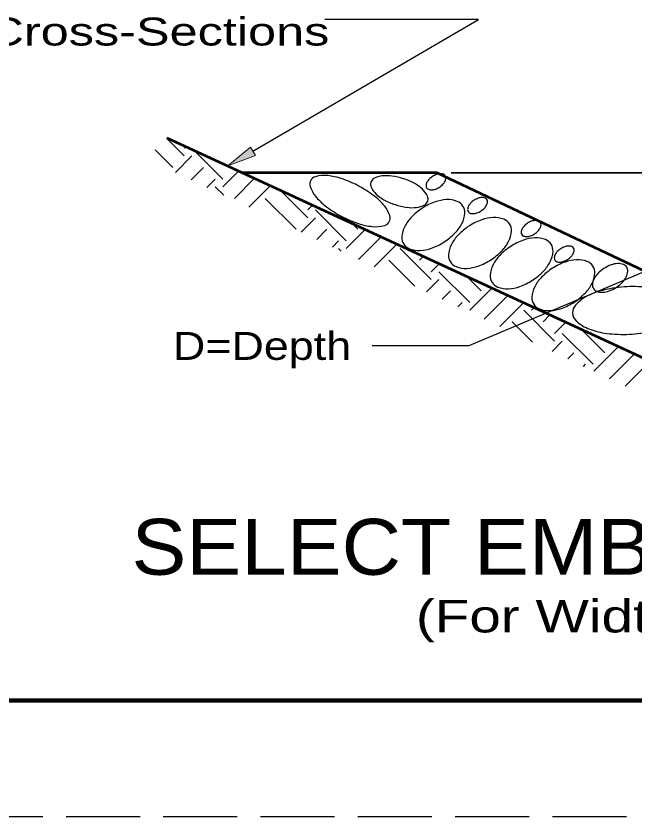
# Model space of a CAD drawing. Extents: x 72.6 to 107.3, y 36.1 to 58.1.
# Drawn here: x 93.671 to 96.33, y 36.08 to 39.52 of the extents above; entities that cross this region are included whole.
import ezdxf

# ---------------------------------------------------------------- set-up
doc = ezdxf.new("R2010")
doc.units = 0
doc.header["$LTSCALE"] = 0.053
doc.linetypes.add('LONG_DASHED', pattern=[7.5, 6, -1.5])
for name, color, linetype, lineweight in [('1', 7, 'Continuous', 35), ('3', 7, 'Continuous', 13), ('4', 7, 'Continuous', 25), ('6', 7, 'Continuous', 13)]:
    doc.layers.add(name, color=color, linetype=linetype, lineweight=lineweight)

msp = doc.modelspace()

# ---------------------------------------------------------------- hatches: boundary and pattern name
at = {"layer": '3'}
msp.add_hatch(color=256, dxfattribs=at).paths.add_polyline_path([(94.69917, 38.92083), (94.67825, 38.95683), (94.58075, 38.87583), (94.58075, 38.87583)])

# ---------------------------------------------------------------- linework, layer by layer
at = {"layer": '1', "lineweight": 25}
for p, q in [((94.39383, 38.91867), (94.31708, 38.9955)), ((94.39383, 38.91867), (94.31708, 38.9955)), ((94.34408, 38.869), (94.2685, 38.94458)), ((94.34408, 38.869), (94.2685, 38.94458)), ((94.39383, 38.95183), (94.40092, 38.95892)), ((94.39383, 38.95183), (94.40092, 38.95892)), ((94.55958, 38.81925), (94.43625, 38.94258)), ((94.55958, 38.81925), (94.43625, 38.94258)), ((94.35608, 38.84783), (94.427, 38.91867)), ((94.35608, 38.84783), (94.427, 38.91867)), ((94.4235, 38.81575), (94.47667, 38.869)), ((94.4235, 38.81575), (94.47667, 38.869)), ((94.55958, 38.78608), (94.62758, 38.85417)), ((94.55958, 38.78608), (94.62758, 38.85417)), ((94.49092, 38.78375), (94.52642, 38.81925)), ((94.49092, 38.78375), (94.52642, 38.81925)), ((94.60925, 38.73642), (94.69558, 38.82275)), ((94.60925, 38.73642), (94.69558, 38.82275)), ((94.56308, 38.7495), (94.52642, 38.78608)), ((94.56308, 38.7495), (94.52642, 38.78608)), ((94.67067, 38.69833), (94.76358, 38.79133)), ((94.67067, 38.69833), (94.76358, 38.79133)), ((94.92417, 38.6535), (94.806, 38.77175)), ((94.92417, 38.6535), (94.806, 38.77175)), ((94.87442, 38.60383), (94.74183, 38.73642)), ((94.87442, 38.60383), (94.74183, 38.73642)), ((94.87442, 38.73642), (94.877, 38.73892)), ((94.87442, 38.73642), (94.877, 38.73892)), ((94.92417, 38.68667), (94.945, 38.7075)), ((94.92417, 38.68667), (94.945, 38.7075)), ((95.08992, 38.55408), (94.95733, 38.68667)), ((95.08992, 38.55408), (94.95733, 38.68667)), ((94.89533, 38.59158), (94.95733, 38.6535)), ((94.89533, 38.59158), (94.95733, 38.6535)), ((95.13958, 38.60383), (95.11408, 38.62933)), ((95.13958, 38.60383), (95.11408, 38.62933)), ((94.96275, 38.55958), (95.007, 38.60383)), ((94.96275, 38.55958), (95.007, 38.60383)), ((95.08992, 38.52092), (95.17167, 38.60275)), ((95.08992, 38.52092), (95.17167, 38.60275)), ((95.1425, 38.47417), (95.23967, 38.57125)), ((95.1425, 38.47417), (95.23967, 38.57125)), ((95.03017, 38.5275), (95.05675, 38.55408)), ((95.03017, 38.5275), (95.05675, 38.55408)), ((95.20992, 38.44208), (95.30767, 38.53983)), ((95.20992, 38.44208), (95.30767, 38.53983)), ((95.06825, 38.50942), (95.05675, 38.52092)), ((95.06825, 38.50942), (95.05675, 38.52092)), ((95.4545, 38.38833), (95.32192, 38.52092)), ((95.4545, 38.38833), (95.32192, 38.52092)), ((95.38408, 38.35942), (95.27217, 38.47125)), ((95.38408, 38.35942), (95.27217, 38.47125)), ((95.40475, 38.47125), (95.421, 38.4875)), ((95.40475, 38.47125), (95.421, 38.4875)), ((95.4545, 38.4215), (95.489, 38.456)), ((95.4545, 38.4215), (95.489, 38.456)), ((95.62025, 38.28892), (95.48767, 38.4215)), ((95.62025, 38.28892), (95.48767, 38.4215)), ((95.43458, 38.33533), (95.48767, 38.38833)), ((95.43458, 38.33533), (95.48767, 38.38833)), ((95.66992, 38.33867), (95.60717, 38.40142)), ((95.66992, 38.33867), (95.60717, 38.40142)), ((95.502, 38.30333), (95.53733, 38.33867)), ((95.502, 38.30333), (95.53733, 38.33867)), ((95.62025, 38.25575), (95.71575, 38.35125)), ((95.62025, 38.25575), (95.71575, 38.35125)), ((95.68175, 38.21792), (95.78375, 38.31983)), ((95.68175, 38.21792), (95.78375, 38.31983)), ((95.56942, 38.27125), (95.58708, 38.28892)), ((95.56942, 38.27125), (95.58708, 38.28892)), ((95.74917, 38.18592), (95.85175, 38.28842)), ((95.74917, 38.18592), (95.85175, 38.28842)), ((95.98483, 38.12317), (95.85225, 38.25575)), ((95.98483, 38.12317), (95.85225, 38.25575)), ((95.88542, 38.25575), (95.89708, 38.2675)), ((95.88542, 38.25575), (95.89708, 38.2675)), ((95.93508, 38.20608), (95.96508, 38.236)), ((95.93508, 38.20608), (95.96508, 38.236)), ((95.88925, 38.11933), (95.8025, 38.20608)), ((95.88925, 38.11933), (95.8025, 38.20608)), ((95.98483, 38.15633), (96.03308, 38.20458)), ((95.98483, 38.15633), (96.03308, 38.20458)), ((96.15058, 38.02375), (96.018, 38.15633)), ((96.15058, 38.02375), (96.018, 38.15633)), ((96.20025, 38.0735), (96.10017, 38.17358)), ((96.20025, 38.0735), (96.10017, 38.17358)), ((95.97392, 38.07908), (96.018, 38.12317)), ((95.97392, 38.07908), (96.018, 38.12317)), ((96.15367, 37.99367), (96.25975, 38.09983)), ((96.15367, 37.99367), (96.25975, 38.09983)), ((96.04133, 38.04708), (96.06767, 38.0735)), ((96.04133, 38.04708), (96.06767, 38.0735)), ((96.22108, 37.96167), (96.32775, 38.06842)), ((96.22108, 37.96167), (96.32775, 38.06842)), ((96.10867, 38.01508), (96.11742, 38.02375)), ((96.10867, 38.01508), (96.11742, 38.02375)), ((96.28842, 37.92967), (96.38258, 38.02375)), ((96.28842, 37.92967), (96.38258, 38.02375))]:
    msp.add_line(p, q, dxfattribs=at)
at = {"layer": '1'}
msp.add_line((95.54108, 38.84625), (96.96983, 38.84625), dxfattribs=at)
at = {"layer": '1', "linetype": 'LONG_DASHED', "lineweight": 25}
msp.add_line((107.16175, 36.07983), (72.62475, 36.07983), dxfattribs=at)
at = {"layer": '1', "lineweight": 158}
msp.add_lwpolyline([(107.07842, 57.57983), (107.07842, 36.57983), (74.57842, 36.57983)], dxfattribs=at)
at = {"layer": '1', "lineweight": 53}
for points in [[(94.3185, 38.997), (96.51967, 37.97967), (97.50133, 37.97967), (99.23892, 38.94783)], [(94.3185, 38.997), (96.51967, 37.97967), (97.50133, 37.97967), (99.23892, 38.94783)], [(98.934, 38.77792), (98.19075, 38.77792), (97.43333, 38.41042), (96.39892, 38.41042), (95.47858, 38.84625), (94.64467, 38.84625)]]:
    msp.add_lwpolyline(points, dxfattribs=at)
at = {"layer": '3', "lineweight": 25}
for points in [[(94.68875, 38.93883), (95.65775, 39.50425), (94.99808, 39.50425)], [(96.67475, 38.54975), (95.617, 38.10283), (95.20167, 38.10283)]]:
    msp.add_lwpolyline(points, dxfattribs=at)
at = {"layer": '3'}
msp.add_lwpolyline([(94.69917, 38.92083), (94.67825, 38.95683), (94.58075, 38.87583), (94.58075, 38.87583)], close=True, dxfattribs=at)
at = {"layer": '4'}
for centre, radius, start, end in [((94.99567, 38.69358), 0.14126, 83.86584, 105.88195), ((94.99567, 38.69358), 0.14126, 83.86584, 105.88195), ((94.98067, 38.55675), 0.2789, 71.63396, 83.81593), ((94.98067, 38.55675), 0.2789, 71.63396, 83.81593), ((95.50549, 38.76059), 0.08321, 109.47631, 122.81482), ((95.49602, 38.78738), 0.05478, 93.02881, 109.47763), ((95.49497, 38.80734), 0.0348, 68.73244, 93.05444), ((95.50169, 38.82464), 0.01624, 32.82904, 68.71961), ((94.966, 38.79767), 0.03298, 152.31131, 198.89128), ((94.966, 38.79767), 0.03298, 152.31131, 198.89128), ((94.966, 38.79775), 0.03288, 105.85731, 152.43728), ((94.966, 38.79775), 0.03288, 105.85731, 152.43728), ((94.91542, 38.36083), 0.48538, 62.38313, 71.60529), ((94.91542, 38.36083), 0.48538, 62.38313, 71.60529), ((95.223, 38.7965), 0.02878, 161.82859, 204.14867), ((95.223, 38.7965), 0.02878, 161.82859, 204.14867), ((95.22292, 38.7965), 0.0287, 119.38842, 161.7085), ((95.22292, 38.7965), 0.0287, 119.38842, 161.7085), ((95.25442, 38.74058), 0.09285, 96.17876, 119.3982), ((95.25442, 38.74058), 0.09285, 96.17876, 119.3982), ((95.26267, 38.66483), 0.16904, 82.39924, 96.18902), ((95.26267, 38.66483), 0.16904, 82.39924, 96.18902), ((95.24808, 38.55308), 0.28175, 71.79973, 82.47057), ((95.24808, 38.55308), 0.28175, 71.79973, 82.47057), ((95.24767, 38.55325), 0.28172, 61.0352, 71.70604), ((95.24767, 38.55325), 0.28172, 61.0352, 71.70604), ((95.30233, 38.65175), 0.16906, 47.29394, 61.08373), ((95.30233, 38.65175), 0.16906, 47.29394, 61.08373), ((95.46728, 38.78949), 0.03483, 152.62903, 176.95103), ((95.48497, 38.78031), 0.05476, 136.15944, 152.60826), ((95.50549, 38.76056), 0.08322, 122.79611, 136.13461), ((95.46536, 38.83487), 0.05489, 316.13726, 332.58607), ((95.48321, 38.82561), 0.03477, 332.60197, 356.92397), ((95.50166, 38.82461), 0.0163, 356.96675, 32.85731), ((95.06825, 38.83308), 0.14118, 199.04439, 221.0605), ((95.06825, 38.83308), 0.14118, 199.04439, 221.0605), ((94.91558, 38.361), 0.48517, 53.17592, 62.39808), ((94.91558, 38.361), 0.48517, 53.17592, 62.39808), ((95.28142, 38.8225), 0.09274, 204.03205, 227.25149), ((95.28142, 38.8225), 0.09274, 204.03205, 227.25149), ((95.35408, 38.70792), 0.09274, 24.03205, 47.25149), ((95.35408, 38.70792), 0.09274, 24.03205, 47.25149), ((95.44872, 38.79044), 0.01624, 176.85974, 212.7503), ((95.44872, 38.79049), 0.01627, 212.92432, 248.81488), ((95.45552, 38.80773), 0.03481, 248.63072, 272.95272), ((95.45441, 38.82769), 0.05478, 273.02881, 289.47763), ((95.44495, 38.85448), 0.08321, 289.47631, 302.81482), ((95.44495, 38.8544), 0.08314, 302.84584, 316.18434), ((95.17208, 38.92325), 0.27869, 221.02166, 233.20363), ((95.17208, 38.92325), 0.27869, 221.02166, 233.20363), ((95.0395, 38.52617), 0.27869, 41.02166, 53.20363), ((95.0395, 38.52617), 0.27869, 41.02166, 53.20363), ((95.33317, 38.87867), 0.16906, 227.29394, 241.08372), ((95.33317, 38.87867), 0.16906, 227.29394, 241.08372), ((95.4125, 38.73392), 0.02878, 341.82859, 24.14867), ((95.4125, 38.73392), 0.02878, 341.82859, 24.14867), ((95.5295, 38.55783), 0.17343, 93.01003, 109.45885), ((95.526, 38.62133), 0.10981, 68.6142, 92.93621), ((95.68424, 38.65842), 0.08321, 109.47631, 122.81482), ((95.67477, 38.68521), 0.05478, 93.02881, 109.47763), ((95.67372, 38.70517), 0.0348, 68.73244, 93.05444), ((95.68044, 38.72247), 0.01624, 32.82904, 68.71961), ((95.68041, 38.72244), 0.0163, 356.96675, 32.85731), ((95.2965, 39.08842), 0.48545, 233.12416, 242.34632), ((95.2965, 39.08842), 0.48545, 233.12416, 242.34632), ((95.14308, 38.6165), 0.14126, 18.92346, 40.93957), ((95.14308, 38.6165), 0.14126, 18.92346, 40.93957), ((95.38783, 38.97717), 0.28172, 241.0352, 251.70604), ((95.38783, 38.97717), 0.28172, 241.0352, 251.70604), ((95.38783, 38.97725), 0.28186, 251.71093, 262.38176), ((95.38783, 38.97725), 0.28186, 251.71093, 262.38176), ((95.37283, 38.8655), 0.16904, 262.39924, 276.18902), ((95.37283, 38.8655), 0.16904, 262.39924, 276.18902), ((95.38108, 38.78975), 0.09285, 276.17876, 299.3982), ((95.38108, 38.78975), 0.09285, 276.17876, 299.3982), ((95.55942, 38.47342), 0.26298, 109.47631, 122.81482), ((95.4125, 38.73392), 0.02879, 299.53439, 341.85447), ((95.4125, 38.73392), 0.02879, 299.53439, 341.85447), ((95.5475, 38.67567), 0.05143, 32.92432, 68.81488), ((95.5475, 38.67583), 0.05133, 356.85974, 32.7503), ((95.64603, 38.68732), 0.03483, 152.62903, 176.95103), ((95.66372, 38.67815), 0.05476, 136.15944, 152.60826), ((95.68424, 38.6584), 0.08322, 122.79611, 136.13461), ((95.64411, 38.7327), 0.05489, 316.13726, 332.58607), ((95.66196, 38.72344), 0.03477, 332.60197, 356.92397), ((95.24558, 38.65158), 0.03286, 332.48041, 19.06037), ((95.24558, 38.65158), 0.03286, 332.48041, 19.06037), ((95.55942, 38.47367), 0.26276, 122.84584, 136.18434), ((95.48883, 38.67883), 0.11007, 332.62903, 356.95103), ((95.62747, 38.68827), 0.01624, 176.85974, 212.7503), ((95.62747, 38.68832), 0.01627, 212.92432, 248.81488), ((95.63427, 38.70557), 0.03481, 248.63072, 272.95272), ((95.63316, 38.72553), 0.05478, 273.02881, 289.47763), ((95.6237, 38.75232), 0.08321, 289.47631, 302.81482), ((95.6237, 38.75224), 0.08314, 302.84584, 316.18434), ((95.29567, 39.0885), 0.48517, 242.43947, 251.66163), ((95.29567, 39.0885), 0.48517, 242.43947, 251.66163), ((95.23083, 38.89233), 0.27851, 251.61678, 263.79875), ((95.23083, 38.89233), 0.27851, 251.61678, 263.79875), ((95.2455, 38.65167), 0.03303, 285.88367, 332.46364), ((95.2455, 38.65167), 0.03303, 285.88367, 332.46364), ((95.49492, 38.53542), 0.17346, 136.13726, 152.58607), ((95.43292, 38.70783), 0.17306, 316.15944, 332.60826), ((95.76008, 38.39675), 0.26298, 109.47631, 122.81482), ((95.73017, 38.48117), 0.17343, 93.01003, 109.45885), ((95.72667, 38.54467), 0.10981, 68.6142, 92.93621), ((95.74817, 38.599), 0.05143, 32.92432, 68.81488), ((95.91407, 38.55981), 0.08322, 122.79611, 136.13461), ((95.91407, 38.55984), 0.08321, 109.47631, 122.81482), ((95.9046, 38.58663), 0.05478, 93.02881, 109.47763), ((95.90355, 38.60659), 0.0348, 68.73244, 93.05444), ((95.91027, 38.62389), 0.01624, 32.82904, 68.71961), ((95.91025, 38.62386), 0.0163, 356.96675, 32.85731), ((95.21608, 38.75583), 0.14124, 263.77764, 285.79375), ((95.21608, 38.75583), 0.14124, 263.77764, 285.79375), ((95.4385, 38.56467), 0.10988, 152.60197, 176.92398), ((95.76008, 38.397), 0.26276, 122.84584, 136.18434), ((95.6895, 38.60217), 0.11007, 332.62903, 356.95103), ((95.74817, 38.59917), 0.05133, 356.85974, 32.7503), ((95.87586, 38.58874), 0.03483, 152.62903, 176.95103), ((95.89356, 38.57956), 0.05476, 136.15944, 152.60826), ((95.85353, 38.65365), 0.08314, 302.84584, 316.18434), ((95.87394, 38.63412), 0.05489, 316.13726, 332.58607), ((95.89179, 38.62486), 0.03477, 332.60197, 356.92397), ((95.38017, 38.56783), 0.0515, 176.96675, 212.85731), ((95.36808, 38.77025), 0.26303, 302.79611, 316.13461), ((95.69558, 38.45875), 0.17346, 136.13726, 152.58607), ((95.8573, 38.58969), 0.01624, 176.85974, 212.7503), ((95.8573, 38.58974), 0.01627, 212.92432, 248.81488), ((95.90892, 38.39358), 0.17343, 93.01003, 109.45885), ((95.8641, 38.60698), 0.03481, 248.63072, 272.95272), ((95.863, 38.62694), 0.05478, 273.02881, 289.47763), ((95.85353, 38.65373), 0.08321, 289.47631, 302.81482), ((95.90542, 38.45708), 0.10981, 68.6142, 92.93621), ((95.92692, 38.51142), 0.05143, 32.92432, 68.81488), ((95.38008, 38.56775), 0.05132, 212.82904, 248.71961), ((95.36808, 38.76983), 0.26266, 289.5108, 302.8493), ((95.63917, 38.488), 0.10988, 152.60197, 176.92398), ((95.93883, 38.30942), 0.26276, 122.84584, 136.18434), ((95.63358, 38.63117), 0.17306, 316.15944, 332.60826), ((95.93883, 38.30917), 0.26298, 109.47631, 122.81482), ((95.92692, 38.51158), 0.05133, 356.85974, 32.7503), ((96.0564, 38.45034), 0.08321, 109.47631, 122.81482), ((96.04694, 38.47713), 0.05478, 93.02881, 109.47763), ((96.04588, 38.49709), 0.0348, 68.73244, 93.05444), ((96.05261, 38.51439), 0.01624, 32.82904, 68.71961), ((95.40133, 38.62242), 0.10997, 248.73244, 273.05444), ((95.39808, 38.68575), 0.17343, 273.01003, 289.45885), ((95.58083, 38.49117), 0.0515, 176.96675, 212.85731), ((95.56875, 38.69358), 0.26303, 302.79611, 316.13461), ((95.87433, 38.37117), 0.17346, 136.13726, 152.58607), ((95.86825, 38.51458), 0.11007, 332.62903, 356.95103), ((96.0182, 38.47924), 0.03483, 152.62903, 176.95103), ((96.03589, 38.47006), 0.05476, 136.15944, 152.60826), ((96.0564, 38.45031), 0.08322, 122.79611, 136.13461), ((96.01627, 38.52462), 0.05489, 316.13726, 332.58607), ((96.03412, 38.51536), 0.03477, 332.60197, 356.92397), ((96.05258, 38.51436), 0.0163, 356.96675, 32.85731), ((95.58075, 38.49108), 0.05132, 212.82904, 248.71961), ((95.56875, 38.69317), 0.26266, 289.5108, 302.8493), ((95.81233, 38.54358), 0.17306, 316.15944, 332.60826), ((96.11808, 38.2155), 0.26266, 109.5108, 122.8493), ((96.11808, 38.2155), 0.26266, 109.5108, 122.8493), ((95.99964, 38.48019), 0.01624, 176.85974, 212.7503), ((95.99964, 38.48024), 0.01627, 212.92432, 248.81488), ((96.00644, 38.49748), 0.03481, 248.63072, 272.95272), ((96.00533, 38.51744), 0.05478, 273.02881, 289.47763), ((95.99586, 38.54423), 0.08321, 289.47631, 302.81482), ((96.08808, 38.29958), 0.17343, 93.01003, 109.45885), ((96.08808, 38.29958), 0.17343, 93.01003, 109.45885), ((95.99586, 38.54415), 0.08314, 302.84584, 316.18434), ((96.08483, 38.36292), 0.10997, 68.73244, 93.05444), ((96.08483, 38.36292), 0.10997, 68.73244, 93.05444), ((96.106, 38.41758), 0.05141, 32.71229, 68.60285), ((96.106, 38.41758), 0.05141, 32.71229, 68.60285), ((96.26046, 38.35906), 0.09739, 93.02881, 109.47763), ((96.25859, 38.39455), 0.06186, 68.73244, 93.05444), ((95.602, 38.54575), 0.10997, 248.73244, 273.05444), ((95.59875, 38.60908), 0.17343, 273.01003, 289.45885), ((95.81792, 38.40042), 0.10988, 152.60197, 176.92398), ((95.7475, 38.606), 0.26303, 302.79611, 316.13461), ((96.11808, 38.21508), 0.26303, 122.79611, 136.13461), ((96.11808, 38.21508), 0.26303, 122.79611, 136.13461), ((96.10608, 38.41742), 0.05137, 357.00557, 32.89613), ((96.10608, 38.41742), 0.05137, 357.00557, 32.89613), ((96.27729, 38.31139), 0.14796, 122.79611, 136.13461), ((96.27729, 38.31144), 0.14793, 109.47631, 122.81482), ((96.27054, 38.4253), 0.02887, 32.82904, 68.71961), ((96.23768, 38.42703), 0.06181, 332.60197, 356.92397), ((96.27049, 38.42525), 0.02897, 356.96675, 32.85731), ((95.75958, 38.40358), 0.0515, 176.96675, 212.85731), ((96.0535, 38.27742), 0.17329, 136.21552, 152.66434), ((96.0535, 38.27742), 0.17329, 136.21552, 152.66434), ((96.0475, 38.42058), 0.11007, 332.62903, 356.95103), ((96.0475, 38.42058), 0.11007, 332.62903, 356.95103), ((96.20937, 38.36281), 0.06191, 152.62903, 176.95103), ((96.24082, 38.3465), 0.09735, 136.15944, 152.60826), ((96.20595, 38.44348), 0.09757, 316.13726, 332.58607), ((95.7595, 38.4035), 0.05132, 212.82904, 248.71961), ((95.78075, 38.45817), 0.10997, 248.73244, 273.05444), ((95.7775, 38.5215), 0.17343, 273.01003, 289.45885), ((95.7475, 38.60558), 0.26266, 289.5108, 302.8493), ((95.99717, 38.30642), 0.10988, 152.60197, 176.92398), ((95.99717, 38.30642), 0.10988, 152.60197, 176.92398), ((95.99158, 38.44992), 0.17323, 316.08112, 332.52994), ((95.99158, 38.44992), 0.17323, 316.08112, 332.52994), ((96.17637, 38.3645), 0.02888, 176.85974, 212.7503), ((96.3234, 37.7977), 0.5599, 92.76039, 102.78419), ((96.16967, 38.47836), 0.14793, 289.47631, 302.81482), ((96.16967, 38.47822), 0.1478, 302.84584, 316.18434), ((96.3234, 37.79777), 0.55983, 82.73383, 92.75763), ((95.92675, 38.51167), 0.26276, 302.84584, 316.18434), ((95.92675, 38.51167), 0.26276, 302.84584, 316.18434), ((96.20481, 38.16214), 0.17419, 115.88116, 138.62437), ((96.27244, 38.02288), 0.329, 102.80576, 115.89117), ((96.17637, 38.36459), 0.02893, 212.92432, 248.81488), ((96.18846, 38.39525), 0.06188, 248.63072, 272.95272), ((96.18649, 38.43073), 0.09739, 273.02881, 289.47763), ((95.93867, 38.3095), 0.05133, 176.85974, 212.7503), ((95.93867, 38.3095), 0.05133, 176.85974, 212.7503), ((95.92675, 38.51192), 0.26298, 289.47631, 302.81482), ((95.92675, 38.51192), 0.26298, 289.47631, 302.81482), ((95.93875, 38.3095), 0.05141, 212.71229, 248.60285), ((95.93875, 38.3095), 0.05141, 212.71229, 248.60285), ((95.95992, 38.36417), 0.10997, 248.73244, 273.05444), ((95.95992, 38.36417), 0.10997, 248.73244, 273.05444), ((95.95667, 38.4275), 0.17343, 273.01003, 289.45885), ((95.95667, 38.4275), 0.17343, 273.01003, 289.45885), ((96.1101, 38.24557), 0.04797, 138.57538, 182.72304), ((96.1101, 38.24563), 0.04802, 182.81358, 226.96124), ((96.19617, 38.33764), 0.174, 226.93966, 249.68286), ((96.25017, 38.48303), 0.3291, 249.65869, 262.74409), ((96.27939, 38.71233), 0.56021, 262.73539, 272.75919), ((96.27906, 38.71206), 0.55995, 272.79955, 282.82335)]:
    msp.add_arc(centre, radius, start, end, dxfattribs=at)
at = {"layer": '6'}
msp.add_line((95.47858, 38.84625), (95.47867, 38.84625), dxfattribs=at)

# ---------------------------------------------------------------- texts
at = {"layer": '3'}
for s, height, width, p in [('Cross-Sections', 0.12, 1.35, (93.54833, 39.39283)), ('D=Depth', 0.12, 1.2, (94.34525, 38.04275)), ('SELECT EMBANKMENT CHANNEL', 0.24, 1.1, (94.16717, 37.12008)), ('(For Widths Exceeding 8 Feet)', 0.14, 1.3, (95.38892, 36.87225))]:
    msp.add_text(s, height=height, dxfattribs=dict(at, width=width)).set_placement(p)

doc.saveas('drawing.dxf')
